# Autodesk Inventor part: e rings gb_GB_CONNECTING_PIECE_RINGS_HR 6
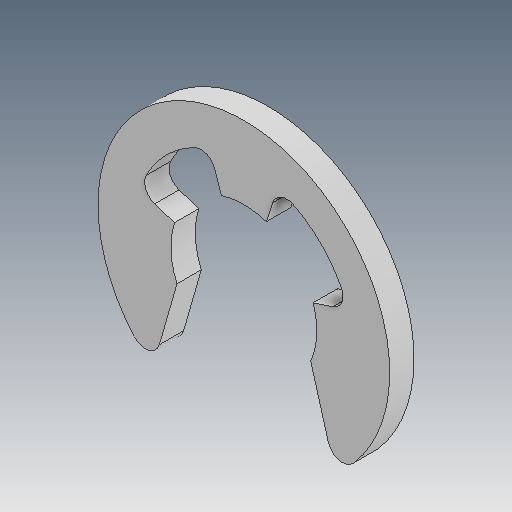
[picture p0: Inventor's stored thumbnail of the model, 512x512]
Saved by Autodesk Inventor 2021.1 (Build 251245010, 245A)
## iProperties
Created: 2019-04
Part Number: e rings gb_GB_CONNECTING_PIECE_RINGS_HR 6
Material: Ogólny
Document SubType Name: Modeling
Designer: user
Density: 1 g/cm^3
Appearance: Domyślna
Author: user
Revision Number: ÈÎºÎ
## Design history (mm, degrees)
feature "ÊäÈë1"
node "Bryła1"
